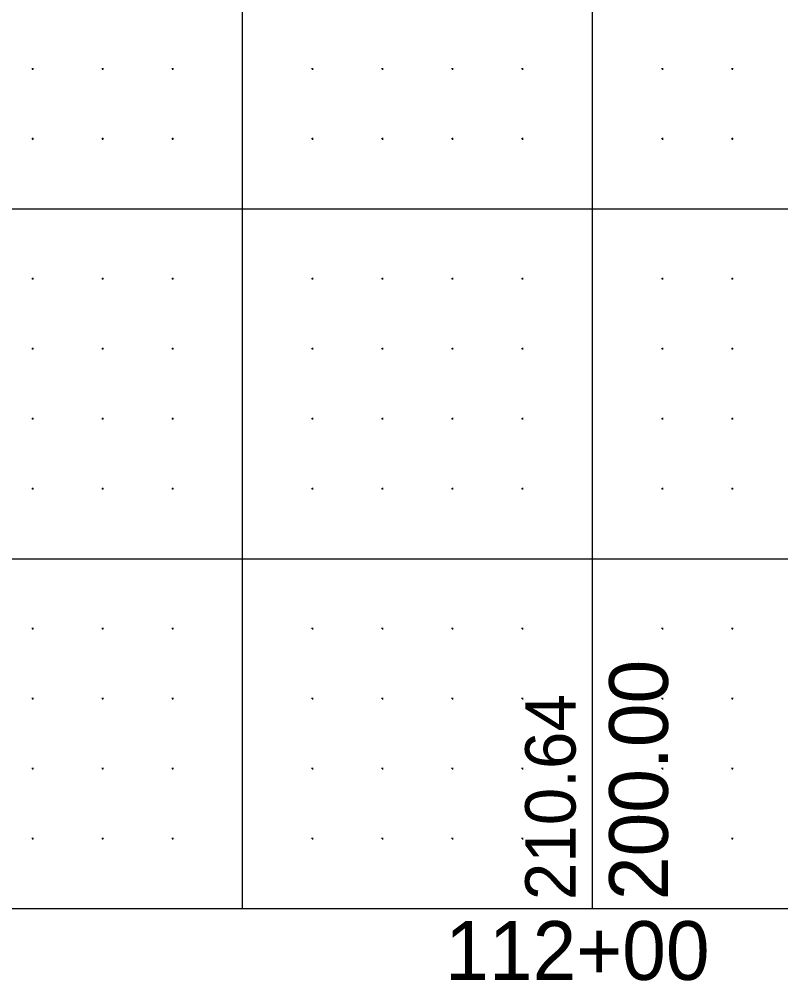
# Model space of a CAD drawing. Extents: x 471 to 2121, y 140 to 650.
# Drawn here: x 1754.2 to 1863, y 139.7 to 277.1 of the extents above; entities that cross this region are included whole.
import ezdxf

# ---------------------------------------------------------------- set-up
doc = ezdxf.new("R2010")
doc.units = 0
for name, color, linetype in [('DSN_DRFT_Border Grid', 7, 'Continuous'), ('DSN_RDWY_Prof Annotation', 7, 'Continuous'), ('EX_Profile Annotation', 7, 'Continuous')]:
    doc.layers.add(name, color=color, linetype=linetype)

msp = doc.modelspace()

# ---------------------------------------------------------------- linework, layer by layer
at = {"layer": 'DSN_DRFT_Border Grid'}
for p, q in [((1786.06, 150), (1786.06, 650)), ((1786.06, 150), (1786.06, 650)), ((1836.06, 150), (1836.06, 650)), ((1836.06, 150), (1836.06, 650)), ((1756.18, 270), (1755.94, 270)), ((1756.18, 270), (1755.94, 270)), ((1756.06, 270.12), (1756.06, 269.88)), ((1756.06, 270.12), (1756.06, 269.88)), ((1766.18, 270), (1765.94, 270)), ((1766.18, 270), (1765.94, 270)), ((1766.06, 270.12), (1766.06, 269.88)), ((1766.06, 270.12), (1766.06, 269.88)), ((1776.18, 270), (1775.94, 270)), ((1776.18, 270), (1775.94, 270)), ((1776.06, 270.12), (1776.06, 269.88)), ((1776.06, 270.12), (1776.06, 269.88)), ((1796.18, 270), (1795.94, 270)), ((1796.18, 270), (1795.94, 270)), ((1796.06, 270.12), (1796.06, 269.88)), ((1796.06, 270.12), (1796.06, 269.88)), ((1806.18, 270), (1805.94, 270)), ((1806.18, 270), (1805.94, 270)), ((1806.06, 270.12), (1806.06, 269.88)), ((1806.06, 270.12), (1806.06, 269.88)), ((1816.18, 270), (1815.94, 270)), ((1816.18, 270), (1815.94, 270)), ((1816.06, 270.12), (1816.06, 269.88)), ((1816.06, 270.12), (1816.06, 269.88)), ((1826.18, 270), (1825.94, 270)), ((1826.18, 270), (1825.94, 270)), ((1826.06, 270.12), (1826.06, 269.88)), ((1826.06, 270.12), (1826.06, 269.88)), ((1846.18, 270), (1845.94, 270)), ((1846.18, 270), (1845.94, 270)), ((1846.06, 270.12), (1846.06, 269.88)), ((1846.06, 270.12), (1846.06, 269.88)), ((1856.18, 270), (1855.94, 270)), ((1856.18, 270), (1855.94, 270)), ((1856.06, 270.12), (1856.06, 269.88)), ((1856.06, 270.12), (1856.06, 269.88)), ((1756.18, 260), (1755.94, 260)), ((1756.18, 260), (1755.94, 260)), ((1756.06, 260.12), (1756.06, 259.88)), ((1756.06, 260.12), (1756.06, 259.88)), ((1766.18, 260), (1765.94, 260)), ((1766.18, 260), (1765.94, 260)), ((1766.06, 260.12), (1766.06, 259.88)), ((1766.06, 260.12), (1766.06, 259.88)), ((1776.18, 260), (1775.94, 260)), ((1776.18, 260), (1775.94, 260)), ((1776.06, 260.12), (1776.06, 259.88)), ((1776.06, 260.12), (1776.06, 259.88)), ((1796.18, 260), (1795.94, 260)), ((1796.18, 260), (1795.94, 260)), ((1796.06, 260.12), (1796.06, 259.88)), ((1796.06, 260.12), (1796.06, 259.88)), ((1806.18, 260), (1805.94, 260)), ((1806.18, 260), (1805.94, 260)), ((1806.06, 260.12), (1806.06, 259.88)), ((1806.06, 260.12), (1806.06, 259.88)), ((1816.18, 260), (1815.94, 260)), ((1816.18, 260), (1815.94, 260)), ((1816.06, 260.12), (1816.06, 259.88)), ((1816.06, 260.12), (1816.06, 259.88)), ((1826.18, 260), (1825.94, 260)), ((1826.18, 260), (1825.94, 260)), ((1826.06, 260.12), (1826.06, 259.88)), ((1826.06, 260.12), (1826.06, 259.88)), ((1846.18, 260), (1845.94, 260)), ((1846.18, 260), (1845.94, 260)), ((1846.06, 260.12), (1846.06, 259.88)), ((1846.06, 260.12), (1846.06, 259.88)), ((1856.18, 260), (1855.94, 260)), ((1856.18, 260), (1855.94, 260)), ((1856.06, 260.12), (1856.06, 259.88)), ((1856.06, 260.12), (1856.06, 259.88)), ((521.06, 250), (2071.06, 250)), ((521.06, 250), (2071.06, 250)), ((1756.18, 240), (1755.94, 240)), ((1756.18, 240), (1755.94, 240)), ((1756.06, 240.12), (1756.06, 239.88)), ((1756.06, 240.12), (1756.06, 239.88)), ((1766.18, 240), (1765.94, 240)), ((1766.18, 240), (1765.94, 240)), ((1766.06, 240.12), (1766.06, 239.88)), ((1766.06, 240.12), (1766.06, 239.88)), ((1776.18, 240), (1775.94, 240)), ((1776.18, 240), (1775.94, 240)), ((1776.06, 240.12), (1776.06, 239.88)), ((1776.06, 240.12), (1776.06, 239.88)), ((1796.18, 240), (1795.94, 240)), ((1796.18, 240), (1795.94, 240)), ((1796.06, 240.12), (1796.06, 239.88)), ((1796.06, 240.12), (1796.06, 239.88)), ((1806.18, 240), (1805.94, 240)), ((1806.18, 240), (1805.94, 240)), ((1806.06, 240.12), (1806.06, 239.88)), ((1806.06, 240.12), (1806.06, 239.88)), ((1816.18, 240), (1815.94, 240)), ((1816.18, 240), (1815.94, 240)), ((1816.06, 240.12), (1816.06, 239.88)), ((1816.06, 240.12), (1816.06, 239.88)), ((1826.18, 240), (1825.94, 240)), ((1826.18, 240), (1825.94, 240)), ((1826.06, 240.12), (1826.06, 239.88)), ((1826.06, 240.12), (1826.06, 239.88)), ((1846.18, 240), (1845.94, 240)), ((1846.18, 240), (1845.94, 240)), ((1846.06, 240.12), (1846.06, 239.88)), ((1846.06, 240.12), (1846.06, 239.88)), ((1856.18, 240), (1855.94, 240)), ((1856.18, 240), (1855.94, 240)), ((1856.06, 240.12), (1856.06, 239.88)), ((1856.06, 240.12), (1856.06, 239.88)), ((1756.18, 230), (1755.94, 230)), ((1756.18, 230), (1755.94, 230)), ((1756.06, 230.12), (1756.06, 229.88)), ((1756.06, 230.12), (1756.06, 229.88)), ((1766.18, 230), (1765.94, 230)), ((1766.18, 230), (1765.94, 230)), ((1766.06, 230.12), (1766.06, 229.88)), ((1766.06, 230.12), (1766.06, 229.88)), ((1776.18, 230), (1775.94, 230)), ((1776.18, 230), (1775.94, 230)), ((1776.06, 230.12), (1776.06, 229.88)), ((1776.06, 230.12), (1776.06, 229.88)), ((1796.18, 230), (1795.94, 230)), ((1796.18, 230), (1795.94, 230)), ((1796.06, 230.12), (1796.06, 229.88)), ((1796.06, 230.12), (1796.06, 229.88)), ((1806.18, 230), (1805.94, 230)), ((1806.18, 230), (1805.94, 230)), ((1806.06, 230.12), (1806.06, 229.88)), ((1806.06, 230.12), (1806.06, 229.88)), ((1816.18, 230), (1815.94, 230)), ((1816.18, 230), (1815.94, 230)), ((1816.06, 230.12), (1816.06, 229.88)), ((1816.06, 230.12), (1816.06, 229.88)), ((1826.18, 230), (1825.94, 230)), ((1826.18, 230), (1825.94, 230)), ((1826.06, 230.12), (1826.06, 229.88)), ((1826.06, 230.12), (1826.06, 229.88)), ((1846.18, 230), (1845.94, 230)), ((1846.18, 230), (1845.94, 230)), ((1846.06, 230.12), (1846.06, 229.88)), ((1846.06, 230.12), (1846.06, 229.88)), ((1856.18, 230), (1855.94, 230)), ((1856.18, 230), (1855.94, 230)), ((1856.06, 230.12), (1856.06, 229.88)), ((1856.06, 230.12), (1856.06, 229.88)), ((1756.18, 220), (1755.94, 220)), ((1756.18, 220), (1755.94, 220)), ((1756.06, 220.12), (1756.06, 219.88)), ((1756.06, 220.12), (1756.06, 219.88)), ((1766.18, 220), (1765.94, 220)), ((1766.18, 220), (1765.94, 220)), ((1766.06, 220.12), (1766.06, 219.88)), ((1766.06, 220.12), (1766.06, 219.88)), ((1776.18, 220), (1775.94, 220)), ((1776.18, 220), (1775.94, 220)), ((1776.06, 220.12), (1776.06, 219.88)), ((1776.06, 220.12), (1776.06, 219.88)), ((1796.18, 220), (1795.94, 220)), ((1796.18, 220), (1795.94, 220)), ((1796.06, 220.12), (1796.06, 219.88)), ((1796.06, 220.12), (1796.06, 219.88)), ((1806.18, 220), (1805.94, 220)), ((1806.18, 220), (1805.94, 220)), ((1806.06, 220.12), (1806.06, 219.88)), ((1806.06, 220.12), (1806.06, 219.88)), ((1816.18, 220), (1815.94, 220)), ((1816.18, 220), (1815.94, 220)), ((1816.06, 220.12), (1816.06, 219.88)), ((1816.06, 220.12), (1816.06, 219.88)), ((1826.18, 220), (1825.94, 220)), ((1826.18, 220), (1825.94, 220)), ((1826.06, 220.12), (1826.06, 219.88)), ((1826.06, 220.12), (1826.06, 219.88)), ((1846.18, 220), (1845.94, 220)), ((1846.18, 220), (1845.94, 220)), ((1846.06, 220.12), (1846.06, 219.88)), ((1846.06, 220.12), (1846.06, 219.88)), ((1856.18, 220), (1855.94, 220)), ((1856.18, 220), (1855.94, 220)), ((1856.06, 220.12), (1856.06, 219.88)), ((1856.06, 220.12), (1856.06, 219.88)), ((1756.18, 210), (1755.94, 210)), ((1756.18, 210), (1755.94, 210)), ((1756.06, 210.12), (1756.06, 209.88)), ((1756.06, 210.12), (1756.06, 209.88)), ((1766.18, 210), (1765.94, 210)), ((1766.18, 210), (1765.94, 210)), ((1766.06, 210.12), (1766.06, 209.88)), ((1766.06, 210.12), (1766.06, 209.88)), ((1776.18, 210), (1775.94, 210)), ((1776.18, 210), (1775.94, 210)), ((1776.06, 210.12), (1776.06, 209.88)), ((1776.06, 210.12), (1776.06, 209.88)), ((1796.18, 210), (1795.94, 210)), ((1796.18, 210), (1795.94, 210)), ((1796.06, 210.12), (1796.06, 209.88)), ((1796.06, 210.12), (1796.06, 209.88)), ((1806.18, 210), (1805.94, 210)), ((1806.18, 210), (1805.94, 210)), ((1806.06, 210.12), (1806.06, 209.88)), ((1806.06, 210.12), (1806.06, 209.88)), ((1816.18, 210), (1815.94, 210)), ((1816.18, 210), (1815.94, 210)), ((1816.06, 210.12), (1816.06, 209.88)), ((1816.06, 210.12), (1816.06, 209.88)), ((1826.18, 210), (1825.94, 210)), ((1826.18, 210), (1825.94, 210)), ((1826.06, 210.12), (1826.06, 209.88)), ((1826.06, 210.12), (1826.06, 209.88)), ((1846.18, 210), (1845.94, 210)), ((1846.18, 210), (1845.94, 210)), ((1846.06, 210.12), (1846.06, 209.88)), ((1846.06, 210.12), (1846.06, 209.88)), ((1856.18, 210), (1855.94, 210)), ((1856.18, 210), (1855.94, 210)), ((1856.06, 210.12), (1856.06, 209.88)), ((1856.06, 210.12), (1856.06, 209.88)), ((521.06, 200), (2071.06, 200)), ((521.06, 200), (2071.06, 200)), ((1756.18, 190), (1755.94, 190)), ((1756.18, 190), (1755.94, 190)), ((1756.06, 190.12), (1756.06, 189.88)), ((1756.06, 190.12), (1756.06, 189.88)), ((1766.18, 190), (1765.94, 190)), ((1766.18, 190), (1765.94, 190)), ((1766.06, 190.12), (1766.06, 189.88)), ((1766.06, 190.12), (1766.06, 189.88)), ((1776.18, 190), (1775.94, 190)), ((1776.18, 190), (1775.94, 190)), ((1776.06, 190.12), (1776.06, 189.88)), ((1776.06, 190.12), (1776.06, 189.88)), ((1796.18, 190), (1795.94, 190)), ((1796.18, 190), (1795.94, 190)), ((1796.06, 190.12), (1796.06, 189.88)), ((1796.06, 190.12), (1796.06, 189.88)), ((1806.18, 190), (1805.94, 190)), ((1806.18, 190), (1805.94, 190)), ((1806.06, 190.12), (1806.06, 189.88)), ((1806.06, 190.12), (1806.06, 189.88)), ((1816.18, 190), (1815.94, 190)), ((1816.18, 190), (1815.94, 190)), ((1816.06, 190.12), (1816.06, 189.88)), ((1816.06, 190.12), (1816.06, 189.88)), ((1826.18, 190), (1825.94, 190)), ((1826.18, 190), (1825.94, 190)), ((1826.06, 190.12), (1826.06, 189.88)), ((1826.06, 190.12), (1826.06, 189.88)), ((1846.18, 190), (1845.94, 190)), ((1846.18, 190), (1845.94, 190)), ((1846.06, 190.12), (1846.06, 189.88)), ((1846.06, 190.12), (1846.06, 189.88)), ((1856.18, 190), (1855.94, 190)), ((1856.18, 190), (1855.94, 190)), ((1856.06, 190.12), (1856.06, 189.88)), ((1856.06, 190.12), (1856.06, 189.88)), ((1756.06, 180.12), (1756.06, 179.88)), ((1756.06, 180.12), (1756.06, 179.88)), ((1766.06, 180.12), (1766.06, 179.88)), ((1766.06, 180.12), (1766.06, 179.88)), ((1776.06, 180.12), (1776.06, 179.88)), ((1776.06, 180.12), (1776.06, 179.88)), ((1796.06, 180.12), (1796.06, 179.88)), ((1796.06, 180.12), (1796.06, 179.88)), ((1806.06, 180.12), (1806.06, 179.88)), ((1806.06, 180.12), (1806.06, 179.88)), ((1816.06, 180.12), (1816.06, 179.88)), ((1816.06, 180.12), (1816.06, 179.88)), ((1826.06, 180.12), (1826.06, 179.88)), ((1826.06, 180.12), (1826.06, 179.88)), ((1846.06, 180.12), (1846.06, 179.88)), ((1846.06, 180.12), (1846.06, 179.88)), ((1856.06, 180.12), (1856.06, 179.88)), ((1856.06, 180.12), (1856.06, 179.88)), ((1756.18, 180), (1755.94, 180)), ((1756.18, 180), (1755.94, 180)), ((1766.18, 180), (1765.94, 180)), ((1766.18, 180), (1765.94, 180)), ((1776.18, 180), (1775.94, 180)), ((1776.18, 180), (1775.94, 180)), ((1796.18, 180), (1795.94, 180)), ((1796.18, 180), (1795.94, 180)), ((1806.18, 180), (1805.94, 180)), ((1806.18, 180), (1805.94, 180)), ((1816.18, 180), (1815.94, 180)), ((1816.18, 180), (1815.94, 180)), ((1826.18, 180), (1825.94, 180)), ((1826.18, 180), (1825.94, 180)), ((1846.18, 180), (1845.94, 180)), ((1846.18, 180), (1845.94, 180)), ((1856.18, 180), (1855.94, 180)), ((1856.18, 180), (1855.94, 180)), ((1756.18, 170), (1755.94, 170)), ((1756.18, 170), (1755.94, 170)), ((1756.06, 170.12), (1756.06, 169.88)), ((1756.06, 170.12), (1756.06, 169.88)), ((1766.18, 170), (1765.94, 170)), ((1766.18, 170), (1765.94, 170)), ((1766.06, 170.12), (1766.06, 169.88)), ((1766.06, 170.12), (1766.06, 169.88)), ((1776.18, 170), (1775.94, 170)), ((1776.18, 170), (1775.94, 170)), ((1776.06, 170.12), (1776.06, 169.88)), ((1776.06, 170.12), (1776.06, 169.88)), ((1796.18, 170), (1795.94, 170)), ((1796.18, 170), (1795.94, 170)), ((1796.06, 170.12), (1796.06, 169.88)), ((1796.06, 170.12), (1796.06, 169.88)), ((1806.18, 170), (1805.94, 170)), ((1806.18, 170), (1805.94, 170)), ((1806.06, 170.12), (1806.06, 169.88)), ((1806.06, 170.12), (1806.06, 169.88)), ((1816.18, 170), (1815.94, 170)), ((1816.18, 170), (1815.94, 170)), ((1816.06, 170.12), (1816.06, 169.88)), ((1816.06, 170.12), (1816.06, 169.88)), ((1826.18, 170), (1825.94, 170)), ((1826.18, 170), (1825.94, 170)), ((1826.06, 170.12), (1826.06, 169.88)), ((1826.06, 170.12), (1826.06, 169.88)), ((1846.18, 170), (1845.94, 170)), ((1846.18, 170), (1845.94, 170)), ((1846.06, 170.12), (1846.06, 169.88)), ((1846.06, 170.12), (1846.06, 169.88)), ((1856.18, 170), (1855.94, 170)), ((1856.18, 170), (1855.94, 170)), ((1856.06, 170.12), (1856.06, 169.88)), ((1856.06, 170.12), (1856.06, 169.88)), ((1756.18, 160), (1755.94, 160)), ((1756.18, 160), (1755.94, 160)), ((1756.06, 160.12), (1756.06, 159.88)), ((1756.06, 160.12), (1756.06, 159.88)), ((1766.18, 160), (1765.94, 160)), ((1766.18, 160), (1765.94, 160)), ((1766.06, 160.12), (1766.06, 159.88)), ((1766.06, 160.12), (1766.06, 159.88)), ((1776.18, 160), (1775.94, 160)), ((1776.18, 160), (1775.94, 160)), ((1776.06, 160.12), (1776.06, 159.88)), ((1776.06, 160.12), (1776.06, 159.88)), ((1796.18, 160), (1795.94, 160)), ((1796.18, 160), (1795.94, 160)), ((1796.06, 160.12), (1796.06, 159.88)), ((1796.06, 160.12), (1796.06, 159.88)), ((1806.18, 160), (1805.94, 160)), ((1806.18, 160), (1805.94, 160)), ((1806.06, 160.12), (1806.06, 159.88)), ((1806.06, 160.12), (1806.06, 159.88)), ((1816.18, 160), (1815.94, 160)), ((1816.18, 160), (1815.94, 160)), ((1816.06, 160.12), (1816.06, 159.88)), ((1816.06, 160.12), (1816.06, 159.88)), ((1826.18, 160), (1825.94, 160)), ((1826.18, 160), (1825.94, 160)), ((1826.06, 160.12), (1826.06, 159.88)), ((1826.06, 160.12), (1826.06, 159.88)), ((1846.18, 160), (1845.94, 160)), ((1846.18, 160), (1845.94, 160)), ((1846.06, 160.12), (1846.06, 159.88)), ((1846.06, 160.12), (1846.06, 159.88)), ((1856.18, 160), (1855.94, 160)), ((1856.18, 160), (1855.94, 160)), ((1856.06, 160.12), (1856.06, 159.88)), ((1856.06, 160.12), (1856.06, 159.88)), ((521.06, 150), (2071.06, 150)), ((521.06, 150), (2071.06, 150))]:
    msp.add_line(p, q, dxfattribs=at)

# ---------------------------------------------------------------- texts
at = {"layer": 'DSN_RDWY_Prof Annotation'}
msp.add_text('200.00', height=8.4, rotation=90, dxfattribs=at).set_placement((1846.86, 151.2))
msp.add_text('112+00', height=8.4, dxfattribs=at).set_placement((1815.02, 139.8))
msp.add_text('112+00', height=8.4, dxfattribs=at).set_placement((1815.02, 139.8))
at = {"layer": 'EX_Profile Annotation'}
msp.add_text('210.64', height=7.2, rotation=90, dxfattribs=at).set_placement((1833.66, 151.2))

doc.saveas('drawing.dxf')
